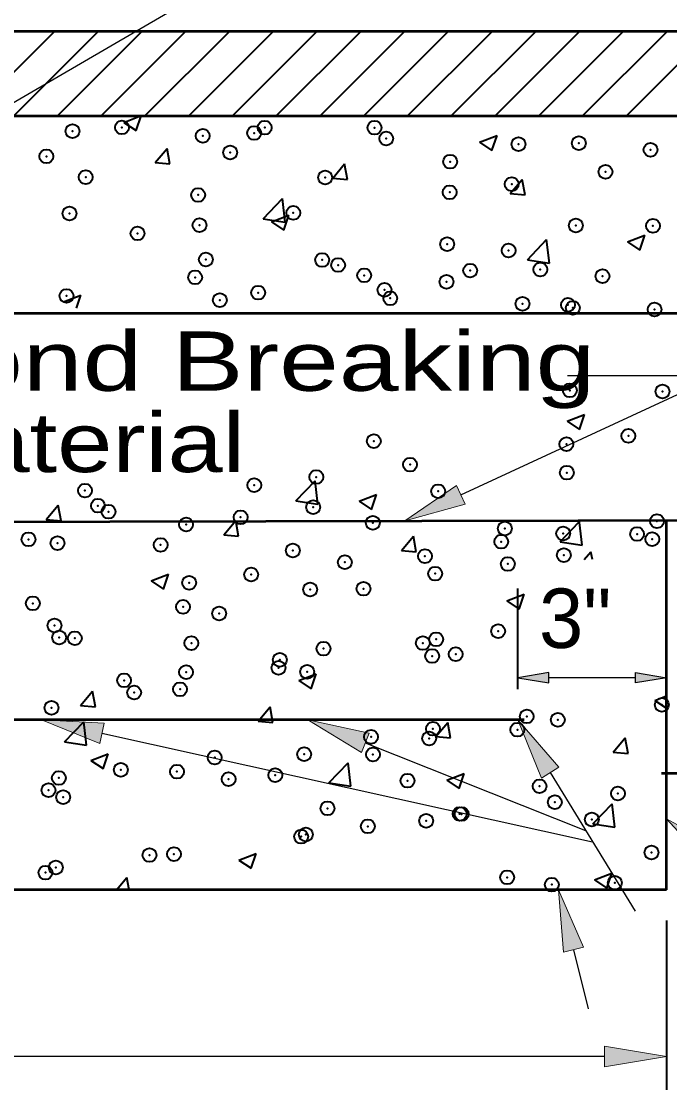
# Model space of a CAD drawing. Extents: x 36.4 to 71.7, y 0.5 to 22.5.
# Drawn here: x 48.735 to 50.045, y 7.982 to 10.127 of the extents above; entities that cross this region are included whole.
import ezdxf

# ---------------------------------------------------------------- set-up
doc = ezdxf.new("R2010")
doc.units = 0
doc.header["$LTSCALE"] = 0.056
doc.header["$PDMODE"] = 32
doc.header["$PDSIZE"] = 0.028
for name, color, linetype, lineweight in [('1', 7, 'Continuous', 40), ('3', 7, 'Continuous', 13), ('6', 7, 'Continuous', 13)]:
    doc.layers.add(name, color=color, linetype=linetype, lineweight=lineweight)

msp = doc.modelspace()

# ---------------------------------------------------------------- hatches: boundary and pattern name
at = {"layer": '1'}
for points in [[(49.80025, 8.79), (49.80025, 8.81083), (49.73775, 8.80033), (49.73775, 8.80033)], [(49.97558, 8.79), (49.97558, 8.81083), (50.03808, 8.80033), (50.03808, 8.80033)], [(49.91308, 8.01433), (49.91308, 8.056), (50.03808, 8.03508), (50.03808, 8.03508)]]:
    msp.add_hatch(color=256, dxfattribs=at).paths.add_polyline_path(points)
at = {"layer": '3'}
for points in [[(49.63175, 9.15108), (49.61425, 9.18892), (49.50958, 9.11742), (49.50958, 9.11742)], [(48.89358, 8.66783), (48.90258, 8.7085), (48.77608, 8.71517), (48.77608, 8.71517)], [(49.422, 8.64958), (49.43742, 8.68833), (49.31358, 8.71517), (49.31358, 8.71517)], [(49.78542, 8.59767), (49.82092, 8.6195), (49.73775, 8.71517), (49.73775, 8.71517)], [(50.124, 8.42217), (50.14958, 8.45508), (50.03808, 8.51525), (50.03808, 8.51525)], [(49.83008, 8.24583), (49.8705, 8.256), (49.81992, 8.37225), (49.81992, 8.37225)]]:
    msp.add_hatch(color=256, dxfattribs=at).paths.add_polyline_path(points)

# ---------------------------------------------------------------- linework, layer by layer
at = {"layer": '1', "lineweight": 53}
for p, q in [((53.64358, 10.10608), (47.51525, 10.10608)), ((47.58758, 9.9355), (53.64358, 9.9355)), ((52.62333, 9.53608), (48.61192, 9.53608)), ((50.03808, 8.37225), (50.03808, 9.11858)), ((49.75083, 8.71517), (46.304, 8.71517)), ((53.64175, 8.60725), (50.02825, 8.60725)), ((50.03808, 8.37225), (46.07633, 8.37225))]:
    msp.add_line(p, q, dxfattribs=at)
at = {"layer": '1'}
for p, q in [((48.63133, 9.9355), (48.80192, 10.10608)), ((48.71975, 9.9355), (48.89033, 10.10608)), ((48.80808, 9.9355), (48.97867, 10.10608)), ((48.8965, 9.9355), (49.06708, 10.10608)), ((48.98483, 9.9355), (49.1555, 10.10608)), ((49.07325, 9.9355), (49.24383, 10.10608)), ((49.16167, 9.9355), (49.33225, 10.10608)), ((49.25, 9.9355), (49.42067, 10.10608)), ((49.33842, 9.9355), (49.509, 10.10608)), ((49.42683, 9.9355), (49.59742, 10.10608)), ((49.51517, 9.9355), (49.68583, 10.10608)), ((49.60358, 9.9355), (49.77417, 10.10608)), ((49.692, 9.9355), (49.86258, 10.10608)), ((49.78033, 9.9355), (49.951, 10.10608)), ((49.86875, 9.9355), (50.03933, 10.10608)), ((49.95717, 9.9355), (50.12775, 10.10608))]:
    msp.add_line(p, q, dxfattribs=at)
at = {"layer": '1', "lineweight": 35}
for p, q in [((48.94233, 9.9225), (48.976, 9.9355)), ((48.96717, 9.90575), (48.97717, 9.9355)), ((48.94233, 9.9225), (48.96717, 9.90575)), ((49.66083, 9.8825), (49.69592, 9.89592)), ((49.68575, 9.86567), (49.69592, 9.89592)), ((49.00542, 9.84125), (49.0295, 9.86992)), ((49.03525, 9.83858), (49.0295, 9.86992)), ((49.66083, 9.8825), (49.68575, 9.86567)), ((49.00542, 9.84125), (49.03525, 9.83858)), ((49.364, 9.80983), (49.38817, 9.83858)), ((49.39392, 9.80725), (49.38817, 9.83858)), ((49.364, 9.80983), (49.39392, 9.80725)), ((49.72267, 9.7785), (49.74675, 9.80717)), ((49.75258, 9.77583), (49.74675, 9.80717)), ((49.2235, 9.72783), (49.26242, 9.76842)), ((49.268, 9.72092), (49.2625, 9.76842)), ((49.72267, 9.7785), (49.7525, 9.77583)), ((49.2235, 9.72783), (49.268, 9.72092)), ((49.24075, 9.72125), (49.27575, 9.73467)), ((49.24075, 9.72125), (49.26567, 9.70442)), ((49.26567, 9.70442), (49.27575, 9.73467)), ((49.95933, 9.68117), (49.99433, 9.69458)), ((49.98417, 9.66442), (49.99433, 9.69458)), ((49.75717, 9.64508), (49.79608, 9.68567)), ((49.80158, 9.63817), (49.79608, 9.68567)), ((49.95933, 9.68117), (49.98417, 9.66442)), ((49.75717, 9.64508), (49.80158, 9.63817)), ((48.82067, 9.55992), (48.85567, 9.57342)), ((48.84692, 9.54733), (48.85567, 9.57342)), ((49.83767, 9.31858), (49.87267, 9.332)), ((49.86258, 9.30183), (49.87267, 9.332)), ((49.83767, 9.31858), (49.8625, 9.30183)), ((49.28983, 9.158), (49.32875, 9.19858)), ((49.33425, 9.15108), (49.32875, 9.19858)), ((49.28983, 9.158), (49.33425, 9.15108)), ((49.41758, 9.15733), (49.45258, 9.17075)), ((49.44242, 9.14058), (49.45258, 9.17075)), ((48.7855, 9.12042), (48.80958, 9.14917)), ((48.81542, 9.11775), (48.80967, 9.14908)), ((49.41758, 9.15733), (49.44242, 9.14058)), ((48.7855, 9.12042), (48.81542, 9.11775)), ((49.16492, 9.11375), (49.16825, 9.11775)), ((49.169, 9.11375), (49.16825, 9.11775)), ((49.86033, 9.11375), (49.86233, 9.11583)), ((49.86258, 9.11375), (49.86233, 9.11583)), ((49.14417, 9.089), (49.16492, 9.11375)), ((49.174, 9.08642), (49.169, 9.11375)), ((49.82342, 9.07525), (49.86033, 9.11375)), ((49.86792, 9.06833), (49.86258, 9.11375)), ((49.14417, 9.089), (49.174, 9.08642)), ((49.50275, 9.05767), (49.52692, 9.08633)), ((49.53267, 9.055), (49.52692, 9.08633)), ((49.82342, 9.07525), (49.86792, 9.06833)), ((49.50275, 9.05767), (49.53267, 9.055)), ((49.87225, 9.03925), (49.8855, 9.055)), ((49.88842, 9.03925), (49.8855, 9.055)), ((48.99742, 8.99608), (49.03242, 9.0095)), ((49.02233, 8.97925), (49.0325, 9.0095)), ((48.99742, 8.99608), (49.02233, 8.97925)), ((49.716, 8.956), (49.751, 8.9695)), ((49.73775, 8.77758), (49.73775, 8.98042)), ((49.74092, 8.93925), (49.751, 8.96942)), ((49.716, 8.956), (49.74092, 8.93925)), ((49.29592, 8.79475), (49.33092, 8.80817)), ((49.29592, 8.79475), (49.32075, 8.778)), ((49.32075, 8.778), (49.33092, 8.80817)), ((48.85492, 8.74433), (48.879, 8.773)), ((48.88475, 8.74167), (48.879, 8.773)), ((50.0145, 8.75475), (50.03808, 8.76375)), ((50.0145, 8.75475), (50.03808, 8.73875)), ((48.85492, 8.74433), (48.88475, 8.74167)), ((49.2135, 8.71292), (49.23758, 8.74167)), ((49.24342, 8.71033), (49.23767, 8.74167)), ((48.8225, 8.67092), (48.86142, 8.7115)), ((48.86692, 8.664), (48.86142, 8.7115)), ((49.2135, 8.71292), (49.24342, 8.71033)), ((49.57217, 8.68158), (49.59625, 8.71025)), ((49.602, 8.67892), (49.59625, 8.71025)), ((48.8225, 8.67092), (48.86692, 8.66408)), ((49.57217, 8.68158), (49.602, 8.67892)), ((49.93075, 8.65017), (49.95492, 8.67892)), ((49.96067, 8.64758), (49.95492, 8.67892)), ((48.87575, 8.6335), (48.91083, 8.64692)), ((48.90067, 8.61667), (48.91083, 8.64692)), ((49.93075, 8.65017), (49.96067, 8.64758)), ((48.87575, 8.6335), (48.90067, 8.61675)), ((49.35608, 8.58817), (49.395, 8.62875)), ((49.40058, 8.58125), (49.395, 8.62875)), ((49.59433, 8.59342), (49.62933, 8.60692)), ((49.61925, 8.57667), (49.62933, 8.60692)), ((49.35608, 8.58817), (49.40058, 8.58125)), ((49.59433, 8.59342), (49.61925, 8.57667)), ((49.88975, 8.50542), (49.92867, 8.546)), ((49.93417, 8.4985), (49.92867, 8.546)), ((49.88975, 8.50542), (49.93417, 8.4985)), ((49.17425, 8.43217), (49.20925, 8.44558)), ((49.17425, 8.43217), (49.19908, 8.41542)), ((49.19908, 8.41542), (49.20925, 8.44558)), ((48.92767, 8.37225), (48.94833, 8.39692)), ((48.95292, 8.37225), (48.94842, 8.39692)), ((49.89283, 8.39217), (49.92783, 8.40558)), ((49.89283, 8.39217), (49.91767, 8.37533)), ((49.91767, 8.37533), (49.92783, 8.40558)), ((50.03808, 8.30967), (50.03808, 7.85517))]:
    msp.add_line(p, q, dxfattribs=at)
at = {"layer": '1', "lineweight": 25}
for p, q in [((49.97558, 8.80042), (49.80025, 8.80042)), ((50.03808, 8.75117), (50.03808, 8.62042)), ((49.91308, 8.03517), (46.20133, 8.03517))]:
    msp.add_line(p, q, dxfattribs=at)
at = {"layer": '1', "lineweight": 53}
msp.add_lwpolyline([(47.51525, 10.10608), (43.59017, 10.10608), (43.59017, 9.827), (43.43175, 9.55683), (43.67933, 9.42175), (43.62983, 9.27633), (44.10525, 9.27633), (46.07633, 9.11), (53.64175, 9.12625)], dxfattribs=at)
at = {"layer": '1', "lineweight": 25}
for points in [[(49.80025, 8.79), (49.80025, 8.81083), (49.73775, 8.80033), (49.73775, 8.80033)], [(49.97558, 8.79), (49.97558, 8.81083), (50.03808, 8.80033), (50.03808, 8.80033)]]:
    msp.add_lwpolyline(points, close=True, dxfattribs=at)
at = {"layer": '1', "lineweight": 13}
msp.add_lwpolyline([(49.91308, 8.01433), (49.91308, 8.056), (50.03808, 8.03508), (50.03808, 8.03508)], close=True, dxfattribs=at)
at = {"layer": '1'}
for p in [(48.83858, 9.90475), (48.93842, 9.91233), (49.1015, 9.89542), (49.20533, 9.901), (49.22667, 9.91183), (49.44842, 9.91175), (49.47225, 9.88975), (49.73917, 9.8785), (49.86117, 9.8805), (48.78575, 9.85383), (49.15683, 9.86175), (50.00608, 9.86717), (49.60142, 9.843), (48.86517, 9.81167), (49.34892, 9.811), (49.91483, 9.82258), (49.7255, 9.79767), (49.09217, 9.77575), (49.60033, 9.78117), (48.8325, 9.73825), (49.2845, 9.73958), (49.09517, 9.71467), (49.85508, 9.714), (50.01092, 9.7135), (48.97, 9.69817), (49.59533, 9.6765), (49.71933, 9.6635), (49.108, 9.6455), (49.34283, 9.6445), (49.37492, 9.63425), (49.64183, 9.623), (49.78333, 9.62533), (49.08608, 9.60933), (49.42775, 9.61342), (49.59392, 9.60042), (49.90875, 9.61167), (49.21342, 9.57842), (49.46875, 9.584), (48.82642, 9.57183), (49.13617, 9.56342), (49.48033, 9.56708), (49.74725, 9.55583), (49.83917, 9.55367), (49.849, 9.54758), (50.01417, 9.54458), (49.84292, 9.38108), (50.03008, 9.37875), (49.44692, 9.27858), (49.96117, 9.289), (49.836, 9.2725), (49.52025, 9.231), (49.83683, 9.21467), (49.20567, 9.18958), (49.33092, 9.206), (48.86375, 9.1785), (49.57717, 9.17717), (48.88992, 9.148), (49.32458, 9.14517), (48.91117, 9.13592), (49.17808, 9.12458), (49.06783, 9.11), (49.445, 9.11333), (49.71183, 9.10208), (50.019, 9.11675), (48.74967, 9.08), (49.82967, 9.09183), (49.97875, 9.09075), (50.0095, 9.08042), (48.80817, 9.0725), (49.01658, 9.06875), (49.7045, 9.07533), (49.2835, 9.05742), (49.55042, 9.04617), (49.83075, 9.04825), (49.38867, 9.03375), (49.71783, 9.03033), (49.19933, 9.00883), (49.57108, 9.01075), (49.07417, 8.99233), (49.3185, 8.97875), (49.42625, 8.98025), (48.75842, 8.95075), (49.06175, 8.9435), (49.13467, 8.93025), (48.80208, 8.906), (49.69808, 8.89458), (48.81167, 8.88175), (48.84308, 8.88017), (49.07858, 8.87042), (49.54608, 8.8705), (49.57292, 8.87808), (49.3455, 8.85917), (49.565, 8.84433), (49.61242, 8.84792), (49.25717, 8.83658), (49.06783, 8.81158), (49.2545, 8.82042), (49.31242, 8.81225), (48.94267, 8.79517), (48.96292, 8.77042), (49.05567, 8.77708), (48.796, 8.73958), (50.02867, 8.74558), (49.75592, 8.72233), (49.81858, 8.71533), (49.56658, 8.69742), (49.737, 8.6955), (49.44142, 8.68092), (49.55892, 8.67783), (49.12567, 8.63933), (49.30633, 8.64583), (49.44542, 8.6455), (48.93625, 8.61442), (49.04958, 8.61067), (48.81108, 8.59792), (49.15383, 8.59542), (49.24808, 8.60367), (49.515, 8.59242), (48.78992, 8.57317), (49.78192, 8.58117), (49.94017, 8.56667), (48.81975, 8.55908), (49.8125, 8.54892), (49.3535, 8.5365), (49.62042, 8.52525), (49.62442, 8.52508), (49.55283, 8.51142), (49.88733, 8.514), (49.30025, 8.47942), (49.30992, 8.48375), (49.43508, 8.50017), (48.99408, 8.44217), (49.0435, 8.44417), (50.008, 8.44725), (48.80475, 8.41717), (48.78383, 8.40667), (49.71642, 8.39717), (49.80642, 8.38242), (49.93383, 8.386)]:
    msp.add_point(p, dxfattribs=at)
at = {"layer": '3', "lineweight": 25}
for p, q in [((48.52608, 9.85067), (50.90675, 11.2355)), ((48.89808, 8.68817), (49.889, 8.46875)), ((49.42967, 8.66892), (49.87492, 8.49175)), ((49.80317, 8.60867), (49.97492, 8.32875)), ((49.85025, 8.251), (49.88017, 8.13142))]:
    msp.add_line(p, q, dxfattribs=at)
msp.add_lwpolyline([(49.623, 9.17), (50.14192, 9.41067), (49.83842, 9.41067)], dxfattribs=at)
at = {"layer": '3'}
for points in [[(49.63175, 9.15108), (49.61425, 9.18892), (49.50958, 9.11742), (49.50958, 9.11742)], [(48.89358, 8.66783), (48.90258, 8.7085), (48.77608, 8.71517), (48.77608, 8.71517)], [(49.422, 8.64958), (49.43742, 8.68833), (49.31358, 8.71517), (49.31358, 8.71517)], [(49.78542, 8.59767), (49.82092, 8.6195), (49.73775, 8.71517), (49.73775, 8.71517)], [(50.124, 8.42217), (50.14958, 8.45508), (50.03808, 8.51525), (50.03808, 8.51525)], [(49.83008, 8.24583), (49.8705, 8.256), (49.81992, 8.37225), (49.81992, 8.37225)]]:
    msp.add_lwpolyline(points, close=True, dxfattribs=at)
at = {"layer": '6', "lineweight": 25}
for p, q in [((49.73775, 8.80042), (49.73783, 8.80042)), ((50.03808, 8.81367), (50.03817, 8.81367)), ((49.73775, 8.71508), (49.73783, 8.71508))]:
    msp.add_line(p, q, dxfattribs=at)
at = {"layer": '6'}
msp.add_line((50.03808, 8.37217), (50.03817, 8.37217), dxfattribs=at)

# ---------------------------------------------------------------- texts
at = {"layer": '3'}
for s, width, p in [('Bond Breaking', 1.35, (48.47325, 9.38017)), ('Material', 1.25, (48.47325, 9.21592))]:
    msp.add_text(s, height=0.12, dxfattribs=dict(at, width=width)).set_placement(p)
msp.add_text('3"', height=0.12, dxfattribs=at).set_placement((49.78075, 8.86067))

doc.saveas('drawing.dxf')
